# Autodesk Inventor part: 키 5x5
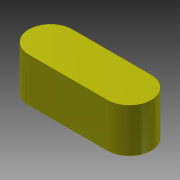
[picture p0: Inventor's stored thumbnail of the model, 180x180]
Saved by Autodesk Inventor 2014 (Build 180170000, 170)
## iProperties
Created: 2016-04
Part Number: 키 5x5
Document SubType Name: Modeling
Designer: mdu
Density: 7.86 g/cm^3
Mass: 2.54015 g
Surface Area: 2.9781 cm^2
Volume: 0.323175 cm^3
Material: 강철, 연강
Appearance: 노란색
Author: mdu
Revision Number: 1
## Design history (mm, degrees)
sketch "스케치1"
  geometry: L1 (-4.5, -2.5)-(4.5, -2.5); L2 (4.5, 2.5)-(-4.5, 2.5); A1 r 2.5 centre (4.5, 0) between (4.5, -2.5) and (4.5, 2.5); A2 r 2.5 centre (-4.5, 0) between (-4.5, 2.5) and (-4.5, -2.5); 2 further points
  constraints: 4 end point, 4 point on circle, 4 tangent, 2 centre point, 1 horizontal, 1 horizontal alignment, 1 midpoint, 1 parallel, 1 vertical alignment
  dimensions: "d0" = 5 distance between parallel lines of L1 L2; "d1" = 14 dimension on A1 A2
extrude "돌출1" new body sketch "스케치1" stored distance "d2" = 5; taper "d3" = 0 deg
chamfer "모따기1" distance "d4" = 0.5; stored, may be unused: second distance "d5" = 2, angle "d6" = 45 deg
node "솔리드1"
other parameters: "d0" = 5
